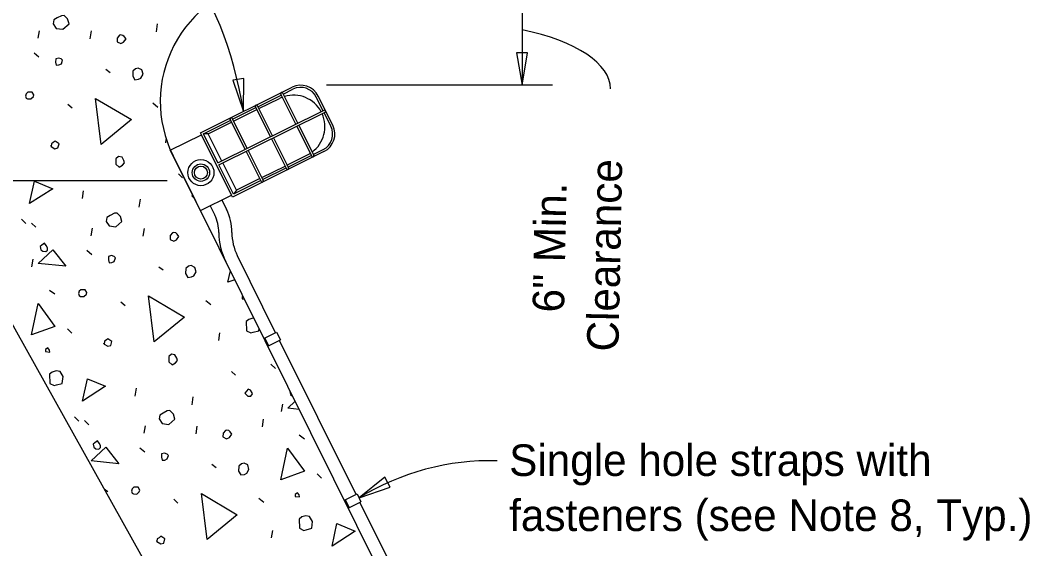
# Model space of a CAD drawing. Extents: x 0 to 30.8, y 0 to 21.2.
# Drawn here: x 3.434 to 8.269, y 14.712 to 17.244 of the extents above; entities that cross this region are included whole.
import ezdxf

# ---------------------------------------------------------------- set-up
doc = ezdxf.new("R2010")
doc.units = 0
for name, color, linetype in [('Dimension', 7, 'Continuous'), ('Lighting', 7, 'Continuous'), ('Miscellaneous', 7, 'Continuous'), ('SteelGirder', 7, 'Continuous'), ('SupstrConc', 7, 'Continuous')]:
    doc.layers.add(name, color=color, linetype=linetype)

msp = doc.modelspace()

# ---------------------------------------------------------------- linework, layer by layer
at = {"layer": 'Dimension'}
for p, q in [((5.8378, 17.4646), (5.8378, 16.9327)), ((5.9837, 16.9327), (4.9003, 16.9327)), ((2.2583, 16.4769), (4.1376, 16.4769))]:
    msp.add_line(p, q, dxfattribs=at)
for points in [[(5.8378, 16.9327), (5.8643, 17.0888), (5.8114, 17.0888)], [(4.5028, 16.8069), (4.5051, 16.9653), (4.4528, 16.9572)], [(5.0568, 14.9559), (5.2065, 15.0078), (5.181, 15.0542)]]:
    msp.add_lwpolyline(points, close=True, dxfattribs=at)
for centre, major_axis, ratio, start_param, end_param in [((3.713, 16.502), (0.0174, -1.3204), 0.616683, 1.795781, 3.141615), ((5.4786, 16.9154), (-0.7827, 0), 0.407451, 3.141527, 4.235533), ((5.6835, 13.8211), (-0.0346, -1.3124), 0.953713, 3.141601, 3.693377)]:
    msp.add_ellipse(centre, major_axis=major_axis, ratio=ratio, start_param=start_param, end_param=end_param, dxfattribs=at)
at = {"layer": 'Lighting'}
for p, q in [((4.2976, 16.705), (4.736, 16.923)), ((4.5727, 16.8301), (4.6846, 16.8858)), ((4.7542, 16.7459), (4.6823, 16.8905)), ((4.7635, 16.7505), (4.6916, 16.8951)), ((4.6939, 16.8904), (4.7406, 16.9137)), ((4.8848, 16.8108), (4.8523, 16.8762)), ((4.9312, 16.7408), (4.8616, 16.8808)), ((4.633, 16.6856), (4.5611, 16.8302)), ((4.6423, 16.6902), (4.5704, 16.8348)), ((4.3811, 16.5604), (4.8894, 16.8132)), ((4.3858, 16.5511), (4.8941, 16.8039)), ((4.4514, 16.7698), (4.5634, 16.8255)), ((4.9219, 16.7362), (4.8894, 16.8015)), ((4.3116, 16.7003), (4.4421, 16.7652)), ((4.5117, 16.6253), (4.4398, 16.7699)), ((4.521, 16.6299), (4.4491, 16.7745)), ((4.7588, 16.7366), (4.8307, 16.592)), ((4.7682, 16.7412), (4.84, 16.5967)), ((4.153, 16.6214), (4.3022, 16.6956)), ((4.3022, 16.6956), (4.2976, 16.705)), ((4.446, 16.4065), (4.3022, 16.6956)), ((4.3811, 16.5604), (4.3116, 16.7003)), ((4.3348, 16.7002), (4.3116, 16.7003)), ((4.3998, 16.5696), (4.3348, 16.7002)), ((4.6376, 16.6763), (4.7095, 16.5317)), ((4.6469, 16.6809), (4.7188, 16.5364)), ((4.2968, 16.3323), (4.153, 16.6214)), ((4.889, 16.6152), (4.4507, 16.3972)), ((4.5163, 16.616), (4.5882, 16.4714)), ((4.5256, 16.6206), (4.5975, 16.4761)), ((4.7165, 16.541), (4.8284, 16.5967)), ((4.8377, 16.6013), (4.8844, 16.6245)), ((4.4553, 16.4112), (4.3858, 16.5511)), ((4.4693, 16.4297), (4.4044, 16.5603)), ((4.5952, 16.4807), (4.7072, 16.5364)), ((4.5859, 16.4761), (4.4553, 16.4112)), ((4.2968, 16.3323), (4.446, 16.4065)), ((4.4507, 16.3972), (4.446, 16.4065)), ((4.4693, 16.4297), (4.4553, 16.4112)), ((4.3434, 16.3555), (4.3658, 16.3104)), ((4.3994, 16.3833), (4.4218, 16.3382)), ((4.6575, 15.7472), (4.4741, 16.1161)), ((5.0429, 14.9723), (4.6761, 15.7099)), ((5.4474, 14.159), (5.0615, 14.935))]:
    msp.add_line(p, q, dxfattribs=at)
for radius in [0.0625, 0.0417, 0.0312]:
    msp.add_circle((4.2995, 16.514), radius, dxfattribs=at)
for centre, radius, start, end in [((4.7777, 16.8391), 0.0937, 26.4422, 116.4422), ((4.687, 16.8928), 0.0052, 26.4422, 206.4423), ((4.7777, 16.8391), 0.0833, 26.4422, 116.4422), ((4.5657, 16.8325), 0.0052, 26.4422, 206.4423), ((4.8918, 16.8085), 0.0052, 296.4087, 116.4422), ((4.4445, 16.7722), 0.0052, 26.4422, 206.4423), ((4.8473, 16.6991), 0.0833, 296.4422, 26.4422), ((4.8473, 16.6991), 0.0937, 296.4422, 26.4422), ((4.8354, 16.5944), 0.0052, 206.4421, 26.4422), ((4.7141, 16.5341), 0.0052, 206.4421, 26.4422), ((4.5929, 16.4737), 0.0052, 206.4421, 26.4422), ((4.198, 16.2269), 0.1875, 0.0537, 26.4422), ((4.198, 16.2269), 0.25, 0.0537, 26.4422), ((4.698, 16.2274), 0.3125, 180.0537, 206.4422), ((4.698, 16.2274), 0.25, 180.0537, 206.2933)]:
    msp.add_arc(centre, radius, start, end, dxfattribs=at)
at = {"layer": 'Miscellaneous'}
for p, q in [((4.0869, 17.1888), (4.0924, 17.2265)), ((3.5204, 17.1586), (3.5265, 17.1939)), ((3.7697, 17.1556), (3.7752, 17.1933)), ((3.5004, 17.0886), (3.5238, 17.0689)), ((3.8449, 17.0101), (3.8646, 16.9946)), ((3.6622, 16.842), (3.6825, 16.8242)), ((4.0696, 16.8477), (4.093, 16.8281)), ((4.5773, 16.8208), (4.6753, 16.8696)), ((4.4561, 16.7605), (4.568, 16.8162)), ((4.3348, 16.7002), (4.4468, 16.7559)), ((4.1311, 16.6571), (4.1339, 16.6735)), ((4.7118, 16.5503), (4.8098, 16.5991)), ((4.5906, 16.49), (4.7025, 16.5457)), ((4.1918, 16.5077), (4.2121, 16.4899)), ((4.5813, 16.4854), (4.4693, 16.4297)), ((3.7317, 16.3896), (3.7371, 16.4273)), ((4.004, 16.3487), (4.0095, 16.3864)), ((3.4398, 16.2907), (3.4608, 16.2704)), ((3.4886, 16.2727), (3.5096, 16.2525)), ((3.7741, 16.212), (3.7802, 16.2473)), ((4.0234, 16.209), (4.0288, 16.2466)), ((4.3406, 16.2422), (4.3408, 16.2437)), ((3.754, 16.142), (3.7774, 16.1223)), ((3.4903, 16.0635), (3.4964, 16.0988)), ((4.0986, 16.0635), (4.1183, 16.048)), ((3.5747, 15.9516), (3.6005, 15.9326)), ((3.9159, 15.8954), (3.9362, 15.8776)), ((4.3233, 15.9011), (4.3466, 15.8815)), ((3.6609, 15.765), (3.6819, 15.7448)), ((4.3847, 15.7105), (4.3908, 15.7458)), ((4.6352, 15.5964), (4.6562, 15.5762)), ((4.4454, 15.5611), (4.4657, 15.5433)), ((3.9853, 15.443), (3.9907, 15.4807)), ((4.2577, 15.4021), (4.2631, 15.4398)), ((4.6858, 15.3693), (4.6918, 15.4046)), ((3.6935, 15.3441), (3.7144, 15.3238)), ((4.5942, 15.2956), (4.5997, 15.3333)), ((3.7423, 15.3261), (3.7632, 15.3059)), ((4.0277, 15.2654), (4.0338, 15.3007)), ((4.277, 15.2623), (4.2824, 15.3)), ((4.7701, 15.2573), (4.7959, 15.2383)), ((4.0077, 15.1954), (4.0311, 15.1757)), ((4.3522, 15.1169), (4.3719, 15.1014)), ((4.8563, 15.0708), (4.8773, 15.0505)), ((3.8359, 14.9994), (3.8541, 14.986)), ((4.1695, 14.9488), (4.1898, 14.931)), ((4.5769, 14.9545), (4.6003, 14.9349)), ((4.6383, 14.7639), (4.6444, 14.7992))]:
    msp.add_line(p, q, dxfattribs=at)
for points in [[(3.5927, 17.2272), (3.6064, 17.205), (3.6386, 17.2007), (3.6679, 17.2266), (3.6614, 17.2508), (3.6441, 17.2668), (3.6314, 17.266), (3.611, 17.2554), (3.5954, 17.246), (3.5927, 17.2272)], [(3.8982, 17.1589), (3.8979, 17.1407), (3.9157, 17.1325), (3.9295, 17.1388), (3.9408, 17.1548), (3.9327, 17.1656), (3.9259, 17.1715), (3.915, 17.1738), (3.9101, 17.1725), (3.8982, 17.1589)], [(3.603, 17.0436), (3.6069, 17.0291), (3.6196, 17.0299), (3.6311, 17.0356), (3.6368, 17.0527), (3.6301, 17.0586), (3.6185, 17.0633), (3.604, 17.0594), (3.603, 17.0436)], [(3.9743, 17.0007), (3.9729, 16.977), (3.9829, 16.959), (4.0004, 16.9611), (4.0118, 16.9668), (4.0224, 16.9852), (4.0166, 17.0069), (3.9989, 17.0151), (3.9868, 17.0119), (3.9743, 17.0007)], [(3.4628, 16.8714), (3.4689, 16.8679), (3.4847, 16.867), (3.4973, 16.8781), (3.5001, 16.8866), (3.4914, 16.8998), (3.4708, 16.8995), (3.4625, 16.8921), (3.4602, 16.8811), (3.4628, 16.8714)], [(3.8225, 16.6495), (3.7945, 16.8697), (3.9667, 16.7683), (3.8225, 16.6495)], [(3.5819, 16.6394), (3.6003, 16.6288), (3.6148, 16.6326), (3.6199, 16.6521), (3.6009, 16.6652), (3.5925, 16.6577), (3.5835, 16.6527), (3.5819, 16.6394), (3.5806, 16.6442)], [(3.8923, 16.5724), (3.892, 16.5542), (3.9086, 16.5406), (3.9242, 16.5499), (3.9344, 16.5604), (3.9311, 16.5725), (3.9218, 16.5881), (3.9054, 16.5914), (3.8928, 16.5803), (3.8923, 16.5724)], [(3.4792, 16.366), (3.5023, 16.4731), (3.5896, 16.4369), (3.4792, 16.366)], [(4.2593, 16.4075), (4.256, 16.4033)], [(4.256, 16.4033), (4.267, 16.3922)], [(3.8463, 16.2806), (3.86, 16.2584), (3.8922, 16.254), (3.9215, 16.28), (3.915, 16.3042), (3.8978, 16.3202), (3.8851, 16.3194), (3.8646, 16.3088), (3.849, 16.2994), (3.8463, 16.2806)], [(4.1519, 16.2123), (4.1516, 16.1941), (4.1693, 16.1859), (4.1831, 16.1922), (4.1944, 16.2082), (4.1863, 16.219), (4.1796, 16.2249), (4.1686, 16.2272), (4.1638, 16.2259), (4.1519, 16.2123)], [(3.5332, 16.1449), (3.5431, 16.1372), (3.5564, 16.1356), (3.5648, 16.143), (3.5646, 16.1533), (3.559, 16.1648), (3.5509, 16.1755), (3.5377, 16.1668), (3.5294, 16.1594), (3.5332, 16.1449)], [(3.5198, 16.0792), (3.5903, 16.1447), (3.6528, 16.0657), (3.5198, 16.0792)], [(3.8567, 16.097), (3.8606, 16.0825), (3.8733, 16.0833), (3.8847, 16.089), (3.8905, 16.1061), (3.8837, 16.112), (3.8721, 16.1167), (3.8576, 16.1128), (3.8567, 16.097)], [(4.2279, 16.0541), (4.2265, 16.0304), (4.2365, 16.0124), (4.2541, 16.0145), (4.2655, 16.0202), (4.2761, 16.0386), (4.2703, 16.0603), (4.2525, 16.0685), (4.2405, 16.0652), (4.2279, 16.0541)], [(4.4291, 15.989), (4.4406, 16.0431)], [(4.4617, 16.0007), (4.4291, 15.989)], [(3.7164, 15.9248), (3.7226, 15.9213), (3.7384, 15.9204), (3.7509, 15.9315), (3.7538, 15.94), (3.7451, 15.9532), (3.7245, 15.9529), (3.7161, 15.9454), (3.7139, 15.9345), (3.7164, 15.9248)], [(4.0762, 15.7029), (4.0482, 15.9231), (4.2203, 15.8217), (4.0762, 15.7029)], [(4.5008, 15.922), (4.497, 15.9192), (4.4972, 15.9089)], [(4.4972, 15.9089), (4.5079, 15.9078)], [(3.4874, 15.7366), (3.5194, 15.8876), (3.6007, 15.7773), (3.4874, 15.7366)], [(4.5538, 15.8155), (4.5479, 15.8163), (4.5285, 15.8111), (4.516, 15.8)], [(4.516, 15.8), (4.5173, 15.7564), (4.5381, 15.7464), (4.5502, 15.7497), (4.5768, 15.7568), (4.5781, 15.7666)], [(3.8356, 15.6928), (3.8539, 15.6822), (3.8684, 15.686), (3.8736, 15.7055), (3.8545, 15.7185), (3.8462, 15.7111), (3.8372, 15.7061), (3.8356, 15.6928), (3.8343, 15.6976)], [(3.5554, 15.6565), (3.5767, 15.6544), (3.5741, 15.6641), (3.566, 15.6749), (3.5552, 15.6668), (3.5554, 15.6565)], [(4.146, 15.6258), (4.1457, 15.6076), (4.1623, 15.5939), (4.1779, 15.6033), (4.188, 15.6138), (4.1848, 15.6259), (4.1754, 15.6415), (4.159, 15.6448), (4.1465, 15.6337), (4.146, 15.6258)], [(3.5742, 15.5477), (3.5756, 15.504), (3.5963, 15.4941), (3.6084, 15.4973), (3.635, 15.5044), (3.6393, 15.5366), (3.6249, 15.5613), (3.6061, 15.564), (3.5868, 15.5588), (3.5742, 15.5477)], [(3.7328, 15.4194), (3.7559, 15.5265), (3.8432, 15.4903), (3.7328, 15.4194)], [(4.5096, 15.4567), (4.5238, 15.4424), (4.539, 15.4438), (4.5467, 15.4537), (4.5454, 15.4585), (4.5367, 15.4717), (4.5251, 15.4763), (4.5174, 15.4665), (4.5096, 15.4567)], [(4.727, 15.4672), (4.7248, 15.4651), (4.7287, 15.4507)], [(4.7287, 15.4507), (4.7385, 15.4429), (4.7391, 15.4429)], [(4.7152, 15.3849), (4.7513, 15.4184)], [(4.7707, 15.3793), (4.7152, 15.3849)], [(4.0999, 15.334), (4.1137, 15.3118), (4.1459, 15.3074), (4.1752, 15.3334), (4.1687, 15.3576), (4.1514, 15.3736), (4.1387, 15.3728), (4.1183, 15.3622), (4.1027, 15.3528), (4.0999, 15.334)], [(4.4055, 15.2657), (4.4052, 15.2475), (4.4229, 15.2393), (4.4368, 15.2456), (4.448, 15.2616), (4.44, 15.2724), (4.4332, 15.2783), (4.4222, 15.2806), (4.4174, 15.2793), (4.4055, 15.2657)], [(3.7734, 15.1326), (3.8439, 15.1981), (3.9065, 15.1191), (3.7734, 15.1326)], [(3.7869, 15.1983), (3.7967, 15.1906), (3.8101, 15.189), (3.8185, 15.1964), (3.8183, 15.2067), (3.8126, 15.2181), (3.8046, 15.2289), (3.7914, 15.2202), (3.783, 15.2128), (3.7869, 15.1983)], [(4.6828, 15.0424), (4.7148, 15.1933), (4.7961, 15.0831), (4.6828, 15.0424)], [(4.1103, 15.1504), (4.1142, 15.1359), (4.1269, 15.1367), (4.1383, 15.1424), (4.1441, 15.1594), (4.1373, 15.1654), (4.1257, 15.1701), (4.1113, 15.1662), (4.1103, 15.1504)], [(4.4816, 15.1075), (4.4801, 15.0838), (4.4901, 15.0658), (4.5077, 15.0679), (4.5191, 15.0736), (4.5297, 15.0919), (4.5239, 15.1137), (4.5062, 15.1219), (4.4941, 15.1186), (4.4816, 15.1075)], [(3.9701, 14.9782), (3.9762, 14.9747), (3.992, 14.9737), (4.0045, 14.9849), (4.0074, 14.9934), (3.9987, 15.0066), (3.9781, 15.0063), (3.9697, 14.9988), (3.9675, 14.9879), (3.9701, 14.9782)], [(4.3298, 14.7563), (4.3018, 14.9765), (4.4739, 14.8751), (4.3298, 14.7563)], [(4.7508, 14.9623), (4.7721, 14.9602), (4.7695, 14.9698), (4.7614, 14.9806), (4.7507, 14.9726), (4.7508, 14.9623)], [(4.7696, 14.8534), (4.771, 14.8098), (4.7918, 14.7998), (4.8038, 14.803), (4.8304, 14.8102), (4.8347, 14.8424), (4.8204, 14.867), (4.8015, 14.8697), (4.7822, 14.8645), (4.7696, 14.8534)], [(4.9283, 14.7251), (4.9513, 14.8322), (5.0386, 14.7961), (4.9283, 14.7251)], [(4.0892, 14.7462), (4.1076, 14.7355), (4.1221, 14.7394), (4.1272, 14.7589), (4.1082, 14.7719), (4.0998, 14.7645), (4.0908, 14.7595), (4.0892, 14.7462), (4.0879, 14.751)]]:
    msp.add_lwpolyline(points, dxfattribs=at)
for start, end in [(110.5219, 116.4422), (28.4157, 106.5369), (306.3475, 24.4687), (296.4422, 302.3625)]:
    msp.add_arc((4.7426, 16.7343), 0.151, start, end, dxfattribs=at)
at = {"layer": 'SteelGirder'}
for p, q in [((4.6016, 15.7194), (4.6622, 15.7496)), ((4.6248, 15.6844), (4.6062, 15.7217)), ((4.6622, 15.7496), (4.6807, 15.7122)), ((4.6201, 15.6821), (4.6807, 15.7122)), ((4.987, 14.9445), (5.0476, 14.9746)), ((5.0102, 14.9095), (4.9916, 14.9468)), ((5.0476, 14.9746), (5.0661, 14.9373)), ((5.0055, 14.9071), (5.0661, 14.9373))]:
    msp.add_line(p, q, dxfattribs=at)
at = {"layer": 'SupstrConc'}
for p, q in [((5.7582, 13.3937), (4.1659, 16.5954)), ((6.5193, 10.1908), (3.0695, 16.3729))]:
    msp.add_line(p, q, dxfattribs=at)
msp.add_arc((4.6882, 16.8551), 0.5833, 98.8325, 206.4422, dxfattribs=at)

# ---------------------------------------------------------------- texts
at = {"layer": 'Dimension'}
for s, p in [('Clearance', (6.2991, 15.6559)), ('6" Min.', (6.0388, 15.843))]:
    msp.add_text(s, height=0.1512, rotation=88.8542, dxfattribs=at).set_placement(p)
for s, p in [('Single hole straps with', (5.7761, 15.0608)), ('fasteners (see Note 8, Typ.)', (5.7761, 14.7968))]:
    msp.add_text(s, height=0.1512, dxfattribs=at).set_placement(p)

doc.saveas('drawing.dxf')
